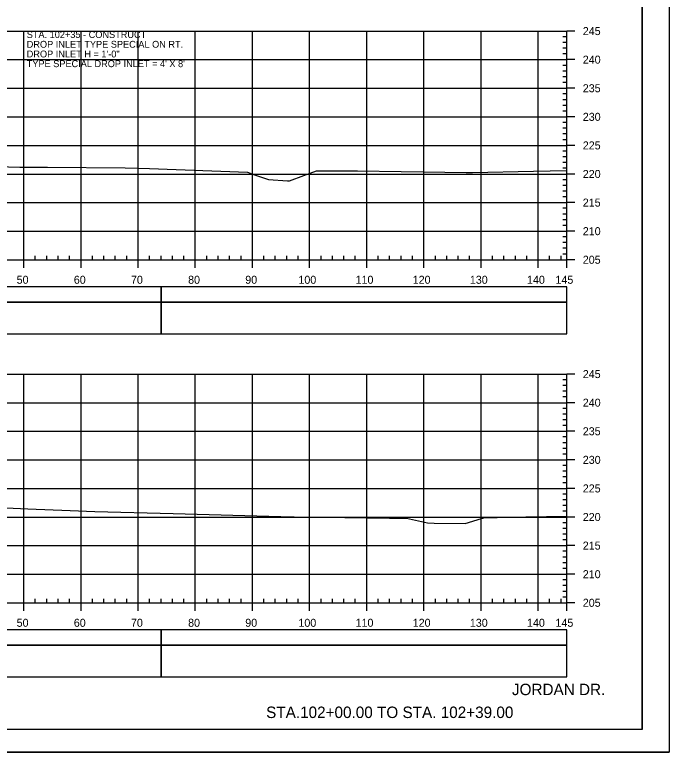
# Model space of a CAD drawing. Extents: x 1386544 to 1388153, y 379785 to 390999.
# Drawn here: x 1386933.6 to 1387048.2, y 380687.9 to 380816.9 of the extents above; entities that cross this region are included whole.
import ezdxf

# ---------------------------------------------------------------- set-up
doc = ezdxf.new("R2010")
doc.units = 0
for name, color, linetype in [('R_Axis', 7, 'Continuous'), ('R_Axis Annot', 7, 'Continuous'), ('R_Border', 7, 'Continuous'), ('R_Draft', 7, 'Continuous'), ('R_Exist Surface', 7, 'Continuous'), ('R_Grid', 7, 'Continuous'), ('R_No Plot', 7, 'Continuous'), ('R_Striping', 7, 'Continuous'), ('R_Water Annot', 7, 'Continuous')]:
    doc.layers.add(name, color=color, linetype=linetype)

msp = doc.modelspace()

# ---------------------------------------------------------------- linework, layer by layer
at = {"layer": 'R_Axis'}
for p, q in [((1387030.24, 380774.07), (1387030.24, 380814.07)), ((1387031.64, 380814.07), (1387030.24, 380814.07)), ((1387030.24, 380813.07), (1387029.54, 380813.07)), ((1387030.24, 380812.07), (1387029.54, 380812.07)), ((1387030.24, 380811.07), (1387029.54, 380811.07)), ((1387030.24, 380810.07), (1387029.54, 380810.07)), ((1387031.64, 380809.07), (1387030.24, 380809.07)), ((1387030.24, 380808.07), (1387029.54, 380808.07)), ((1387030.24, 380807.07), (1387029.54, 380807.07)), ((1387030.24, 380806.07), (1387029.54, 380806.07)), ((1387030.24, 380805.07), (1387029.54, 380805.07)), ((1387031.64, 380804.07), (1387030.24, 380804.07)), ((1387030.24, 380803.07), (1387029.54, 380803.07)), ((1387030.24, 380802.07), (1387029.54, 380802.07)), ((1387030.24, 380801.07), (1387029.54, 380801.07)), ((1387030.24, 380800.07), (1387029.54, 380800.07)), ((1387031.64, 380799.07), (1387030.24, 380799.07)), ((1387030.24, 380798.07), (1387029.54, 380798.07)), ((1387030.24, 380797.07), (1387029.54, 380797.07)), ((1387030.24, 380796.07), (1387029.54, 380796.07)), ((1387030.24, 380795.07), (1387029.54, 380795.07)), ((1387031.64, 380794.07), (1387030.24, 380794.07)), ((1387030.24, 380793.07), (1387029.54, 380793.07)), ((1387030.24, 380792.07), (1387029.54, 380792.07)), ((1387030.24, 380791.07), (1387029.54, 380791.07)), ((1387030.24, 380790.07), (1387029.54, 380790.07)), ((1387030.24, 380788.07), (1387029.54, 380788.07)), ((1387031.64, 380789.07), (1387030.24, 380789.07)), ((1387030.24, 380787.07), (1387029.54, 380787.07)), ((1387030.24, 380786.07), (1387029.54, 380786.07)), ((1387030.24, 380785.07), (1387029.54, 380785.07)), ((1387030.24, 380783.07), (1387029.54, 380783.07)), ((1387031.64, 380784.07), (1387030.24, 380784.07)), ((1387030.24, 380782.07), (1387029.54, 380782.07)), ((1387030.24, 380781.07), (1387029.54, 380781.07)), ((1387030.24, 380780.07), (1387029.54, 380780.07)), ((1387031.64, 380779.07), (1387030.24, 380779.07)), ((1387030.24, 380778.07), (1387029.54, 380778.07)), ((1387030.24, 380777.07), (1387029.54, 380777.07)), ((1387030.24, 380776.07), (1387029.54, 380776.07)), ((1386740.24, 380774.07), (1387030.24, 380774.07)), ((1386935.24, 380772.67), (1386935.24, 380774.07)), ((1386937.24, 380774.07), (1386937.24, 380774.77)), ((1386939.24, 380774.07), (1386939.24, 380774.77)), ((1386941.24, 380774.07), (1386941.24, 380774.77)), ((1386943.24, 380774.07), (1386943.24, 380774.77)), ((1386945.24, 380772.67), (1386945.24, 380774.07)), ((1386947.24, 380774.07), (1386947.24, 380774.77)), ((1386949.24, 380774.07), (1386949.24, 380774.77)), ((1386951.24, 380774.07), (1386951.24, 380774.77)), ((1386953.24, 380774.07), (1386953.24, 380774.77)), ((1386955.24, 380772.67), (1386955.24, 380774.07)), ((1386957.24, 380774.07), (1386957.24, 380774.77)), ((1386959.24, 380774.07), (1386959.24, 380774.77)), ((1386961.24, 380774.07), (1386961.24, 380774.77)), ((1386963.24, 380774.07), (1386963.24, 380774.77)), ((1386965.24, 380772.67), (1386965.24, 380774.07)), ((1386967.24, 380774.07), (1386967.24, 380774.77)), ((1386969.24, 380774.07), (1386969.24, 380774.77)), ((1386971.24, 380774.07), (1386971.24, 380774.77)), ((1386973.24, 380774.07), (1386973.24, 380774.77)), ((1386975.24, 380772.67), (1386975.24, 380774.07)), ((1386977.24, 380774.07), (1386977.24, 380774.77)), ((1386979.24, 380774.07), (1386979.24, 380774.77)), ((1386981.24, 380774.07), (1386981.24, 380774.77)), ((1386983.24, 380774.07), (1386983.24, 380774.77)), ((1386985.24, 380772.67), (1386985.24, 380774.07)), ((1386987.24, 380774.07), (1386987.24, 380774.77)), ((1386989.24, 380774.07), (1386989.24, 380774.77)), ((1386991.24, 380774.07), (1386991.24, 380774.77)), ((1386993.24, 380774.07), (1386993.24, 380774.77)), ((1386995.24, 380772.67), (1386995.24, 380774.07)), ((1386997.24, 380774.07), (1386997.24, 380774.77)), ((1386999.24, 380774.07), (1386999.24, 380774.77)), ((1387001.24, 380774.07), (1387001.24, 380774.77)), ((1387003.24, 380774.07), (1387003.24, 380774.77)), ((1387005.24, 380772.67), (1387005.24, 380774.07)), ((1387007.24, 380774.07), (1387007.24, 380774.77)), ((1387009.24, 380774.07), (1387009.24, 380774.77)), ((1387011.24, 380774.07), (1387011.24, 380774.77)), ((1387013.24, 380774.07), (1387013.24, 380774.77)), ((1387015.24, 380772.67), (1387015.24, 380774.07)), ((1387017.24, 380774.07), (1387017.24, 380774.77)), ((1387019.24, 380774.07), (1387019.24, 380774.77)), ((1387021.24, 380774.07), (1387021.24, 380774.77)), ((1387023.24, 380774.07), (1387023.24, 380774.77)), ((1387025.24, 380772.67), (1387025.24, 380774.07)), ((1387027.24, 380774.07), (1387027.24, 380774.77)), ((1387029.24, 380774.07), (1387029.24, 380774.77)), ((1387030.24, 380775.07), (1387029.54, 380775.07)), ((1387030.24, 380772.67), (1387030.24, 380774.07)), ((1387031.64, 380774.07), (1387030.24, 380774.07)), ((1387030.24, 380714.07), (1387030.24, 380754.07)), ((1387031.64, 380754.07), (1387030.24, 380754.07)), ((1387030.24, 380753.07), (1387029.54, 380753.07)), ((1387030.24, 380752.07), (1387029.54, 380752.07)), ((1387030.24, 380751.07), (1387029.54, 380751.07)), ((1387030.24, 380750.07), (1387029.54, 380750.07)), ((1387030.24, 380748.07), (1387029.54, 380748.07)), ((1387031.64, 380749.07), (1387030.24, 380749.07)), ((1387030.24, 380747.07), (1387029.54, 380747.07)), ((1387030.24, 380746.07), (1387029.54, 380746.07)), ((1387030.24, 380745.07), (1387029.54, 380745.07)), ((1387030.24, 380743.07), (1387029.54, 380743.07)), ((1387031.64, 380744.07), (1387030.24, 380744.07)), ((1387030.24, 380742.07), (1387029.54, 380742.07)), ((1387030.24, 380741.07), (1387029.54, 380741.07)), ((1387030.24, 380740.07), (1387029.54, 380740.07)), ((1387031.64, 380739.07), (1387030.24, 380739.07)), ((1387030.24, 380738.07), (1387029.54, 380738.07)), ((1387030.24, 380737.07), (1387029.54, 380737.07)), ((1387030.24, 380736.07), (1387029.54, 380736.07)), ((1387030.24, 380735.07), (1387029.54, 380735.07)), ((1387031.64, 380734.07), (1387030.24, 380734.07)), ((1387030.24, 380733.07), (1387029.54, 380733.07)), ((1387030.24, 380732.07), (1387029.54, 380732.07)), ((1387030.24, 380731.07), (1387029.54, 380731.07)), ((1387030.24, 380730.07), (1387029.54, 380730.07)), ((1387031.64, 380729.07), (1387030.24, 380729.07)), ((1387030.24, 380728.07), (1387029.54, 380728.07)), ((1387030.24, 380727.07), (1387029.54, 380727.07)), ((1387030.24, 380726.07), (1387029.54, 380726.07)), ((1387030.24, 380725.07), (1387029.54, 380725.07)), ((1387031.64, 380724.07), (1387030.24, 380724.07)), ((1387030.24, 380723.07), (1387029.54, 380723.07)), ((1387030.24, 380722.07), (1387029.54, 380722.07)), ((1387030.24, 380721.07), (1387029.54, 380721.07)), ((1387030.24, 380720.07), (1387029.54, 380720.07)), ((1387031.64, 380719.07), (1387030.24, 380719.07)), ((1387030.24, 380718.07), (1387029.54, 380718.07)), ((1387030.24, 380717.07), (1387029.54, 380717.07)), ((1387030.24, 380716.07), (1387029.54, 380716.07)), ((1386937.24, 380714.07), (1386937.24, 380714.77)), ((1386939.24, 380714.07), (1386939.24, 380714.77)), ((1386941.24, 380714.07), (1386941.24, 380714.77)), ((1386943.24, 380714.07), (1386943.24, 380714.77)), ((1386947.24, 380714.07), (1386947.24, 380714.77)), ((1386949.24, 380714.07), (1386949.24, 380714.77)), ((1386951.24, 380714.07), (1386951.24, 380714.77)), ((1386953.24, 380714.07), (1386953.24, 380714.77)), ((1386957.24, 380714.07), (1386957.24, 380714.77)), ((1386959.24, 380714.07), (1386959.24, 380714.77)), ((1386961.24, 380714.07), (1386961.24, 380714.77)), ((1386963.24, 380714.07), (1386963.24, 380714.77)), ((1386967.24, 380714.07), (1386967.24, 380714.77)), ((1386969.24, 380714.07), (1386969.24, 380714.77)), ((1386971.24, 380714.07), (1386971.24, 380714.77)), ((1386973.24, 380714.07), (1386973.24, 380714.77)), ((1386977.24, 380714.07), (1386977.24, 380714.77)), ((1386979.24, 380714.07), (1386979.24, 380714.77)), ((1386981.24, 380714.07), (1386981.24, 380714.77)), ((1386983.24, 380714.07), (1386983.24, 380714.77)), ((1386987.24, 380714.07), (1386987.24, 380714.77)), ((1386989.24, 380714.07), (1386989.24, 380714.77)), ((1386991.24, 380714.07), (1386991.24, 380714.77)), ((1386993.24, 380714.07), (1386993.24, 380714.77)), ((1386997.24, 380714.07), (1386997.24, 380714.77)), ((1386999.24, 380714.07), (1386999.24, 380714.77)), ((1387001.24, 380714.07), (1387001.24, 380714.77)), ((1387003.24, 380714.07), (1387003.24, 380714.77)), ((1387007.24, 380714.07), (1387007.24, 380714.77)), ((1387009.24, 380714.07), (1387009.24, 380714.77)), ((1387011.24, 380714.07), (1387011.24, 380714.77)), ((1387013.24, 380714.07), (1387013.24, 380714.77)), ((1387017.24, 380714.07), (1387017.24, 380714.77)), ((1387019.24, 380714.07), (1387019.24, 380714.77)), ((1387021.24, 380714.07), (1387021.24, 380714.77)), ((1387023.24, 380714.07), (1387023.24, 380714.77)), ((1387027.24, 380714.07), (1387027.24, 380714.77)), ((1387029.24, 380714.07), (1387029.24, 380714.77)), ((1387030.24, 380715.07), (1387029.54, 380715.07)), ((1386740.24, 380714.07), (1387030.24, 380714.07)), ((1386935.24, 380712.67), (1386935.24, 380714.07)), ((1386945.24, 380712.67), (1386945.24, 380714.07)), ((1386955.24, 380712.67), (1386955.24, 380714.07)), ((1386965.24, 380712.67), (1386965.24, 380714.07)), ((1386975.24, 380712.67), (1386975.24, 380714.07)), ((1386985.24, 380712.67), (1386985.24, 380714.07)), ((1386995.24, 380712.67), (1386995.24, 380714.07)), ((1387005.24, 380712.67), (1387005.24, 380714.07)), ((1387015.24, 380712.67), (1387015.24, 380714.07)), ((1387025.24, 380712.67), (1387025.24, 380714.07)), ((1387030.24, 380712.67), (1387030.24, 380714.07)), ((1387031.64, 380714.07), (1387030.24, 380714.07))]:
    msp.add_line(p, q, dxfattribs=at)
at = {"layer": 'R_Axis Annot'}
for points in [[(1386959.26, 380766.63), (1387030.24, 380766.63), (1387030.24, 380769.34), (1386959.26, 380769.34)], [(1386959.26, 380761.1), (1387030.24, 380761.1), (1387030.24, 380766.63), (1386959.26, 380766.63)], [(1386959.26, 380706.63), (1387030.24, 380706.63), (1387030.24, 380709.34), (1386959.26, 380709.34)], [(1386959.26, 380701.1), (1387030.24, 380701.1), (1387030.24, 380706.63), (1386959.26, 380706.63)]]:
    msp.add_lwpolyline(points, close=True, dxfattribs=at)
at = {"layer": 'R_Border'}
for q in [(1387043.42, 380897.37), (1386727.24, 380691.91)]:
    msp.add_line((1387043.42, 380691.91), q, dxfattribs=at)
at = {"layer": 'R_Exist Surface'}
for points in [[(1386924.43, 380790.54), (1386934.51, 380790.27), (1386936.18, 380790.27), (1386939.39, 380790.27), (1386952.98, 380790.12), (1386957.25, 380790.02), (1386974.37, 380789.39), (1386975.4, 380789), (1386978.02, 380788.09), (1386981.4, 380787.88), (1386981.75, 380787.87), (1386984.23, 380788.79), (1386986.46, 380789.62), (1386988.17, 380789.61), (1386993.6, 380789.61), (1387008.91, 380789.39), (1387012.66, 380789.35), (1387013.77, 380789.36), (1387024.43, 380789.57), (1387030.24, 380789.69)], [(1386926.87, 380730.93), (1386935.93, 380730.48), (1386943.35, 380730.2), (1386947.67, 380730.03), (1386961.38, 380729.66), (1386980.21, 380729.16), (1386982.56, 380729.11), (1386987.5, 380729.04), (1386999.24, 380728.89), (1387002.2, 380728.84), (1387004.28, 380728.41), (1387005.87, 380728.05), (1387007.04, 380728.02), (1387012.44, 380727.94), (1387015.34, 380728.81), (1387015.96, 380729.01), (1387018.03, 380729), (1387019.52, 380729.03), (1387030.24, 380729.23)]]:
    msp.add_lwpolyline(points, dxfattribs=at)
at = {"layer": 'R_Grid'}
for p, q in [((1386740.24, 380814.07), (1387030.24, 380814.07)), ((1386740.24, 380814.07), (1387030.24, 380814.07)), ((1386935.24, 380774.07), (1386935.24, 380814.07)), ((1386935.24, 380774.07), (1386935.24, 380814.07)), ((1386945.24, 380774.07), (1386945.24, 380814.07)), ((1386945.24, 380774.07), (1386945.24, 380814.07)), ((1386955.24, 380774.07), (1386955.24, 380814.07)), ((1386955.24, 380774.07), (1386955.24, 380814.07)), ((1386965.24, 380774.07), (1386965.24, 380814.07)), ((1386965.24, 380774.07), (1386965.24, 380814.07)), ((1386975.24, 380774.07), (1386975.24, 380814.07)), ((1386975.24, 380774.07), (1386975.24, 380814.07)), ((1386985.24, 380774.07), (1386985.24, 380814.07)), ((1386985.24, 380774.07), (1386985.24, 380814.07)), ((1386995.24, 380774.07), (1386995.24, 380814.07)), ((1386995.24, 380774.07), (1386995.24, 380814.07)), ((1387005.24, 380774.07), (1387005.24, 380814.07)), ((1387005.24, 380774.07), (1387005.24, 380814.07)), ((1387015.24, 380774.07), (1387015.24, 380814.07)), ((1387015.24, 380774.07), (1387015.24, 380814.07)), ((1387025.24, 380774.07), (1387025.24, 380814.07)), ((1387025.24, 380774.07), (1387025.24, 380814.07)), ((1387030.24, 380774.07), (1387030.24, 380814.07)), ((1387030.24, 380774.07), (1387030.24, 380814.07)), ((1386740.24, 380809.07), (1387030.24, 380809.07)), ((1386740.24, 380809.07), (1387030.24, 380809.07)), ((1386740.24, 380804.07), (1387030.24, 380804.07)), ((1386740.24, 380804.07), (1387030.24, 380804.07)), ((1386740.24, 380799.07), (1387030.24, 380799.07)), ((1386740.24, 380799.07), (1387030.24, 380799.07)), ((1386740.24, 380794.07), (1387030.24, 380794.07)), ((1386740.24, 380794.07), (1387030.24, 380794.07)), ((1386740.24, 380789.07), (1387030.24, 380789.07)), ((1386740.24, 380789.07), (1387030.24, 380789.07)), ((1386740.24, 380784.07), (1387030.24, 380784.07)), ((1386740.24, 380784.07), (1387030.24, 380784.07)), ((1386740.24, 380779.07), (1387030.24, 380779.07)), ((1386740.24, 380779.07), (1387030.24, 380779.07)), ((1386740.24, 380774.07), (1387030.24, 380774.07)), ((1386740.24, 380774.07), (1387030.24, 380774.07)), ((1386740.24, 380754.07), (1387030.24, 380754.07)), ((1386935.24, 380714.07), (1386935.24, 380754.07)), ((1386945.24, 380714.07), (1386945.24, 380754.07)), ((1386955.24, 380714.07), (1386955.24, 380754.07)), ((1386965.24, 380714.07), (1386965.24, 380754.07)), ((1386975.24, 380714.07), (1386975.24, 380754.07)), ((1386985.24, 380714.07), (1386985.24, 380754.07)), ((1386995.24, 380714.07), (1386995.24, 380754.07)), ((1387005.24, 380714.07), (1387005.24, 380754.07)), ((1387015.24, 380714.07), (1387015.24, 380754.07)), ((1387025.24, 380714.07), (1387025.24, 380754.07)), ((1387030.24, 380714.07), (1387030.24, 380754.07)), ((1386740.24, 380749.07), (1387030.24, 380749.07)), ((1386740.24, 380744.07), (1387030.24, 380744.07)), ((1386740.24, 380739.07), (1387030.24, 380739.07)), ((1386740.24, 380734.07), (1387030.24, 380734.07)), ((1386740.24, 380729.07), (1387030.24, 380729.07)), ((1386740.24, 380724.07), (1387030.24, 380724.07)), ((1386740.24, 380719.07), (1387030.24, 380719.07)), ((1386740.24, 380714.07), (1387030.24, 380714.07))]:
    msp.add_line(p, q, dxfattribs=at)
at = {"layer": 'R_No Plot'}
msp.add_line((1386714.84, 380687.93), (1387048.17, 380687.93), dxfattribs=at)
for points in [[(1386714.83, 380901.26), (1387048.17, 380901.26), (1387048.17, 380687.92), (1386714.83, 380687.92)], [(1386961.16, 380897.37), (1386980.78, 380897.37), (1386980.78, 380887.49), (1386996.89, 380887.49), (1387020.09, 380887.49), (1387020.09, 380863.15), (1387043.42, 380863.15), (1387043.42, 380691.91), (1386727.24, 380691.91), (1386727.24, 380897.37)]]:
    msp.add_lwpolyline(points, close=True, dxfattribs=at)
at = {"layer": 'R_Striping'}
for points in [[(1386927.92, 380766.63), (1386959.26, 380766.63), (1386959.26, 380769.34), (1386927.92, 380769.34)], [(1386927.92, 380761.11), (1386959.26, 380761.11), (1386959.26, 380766.63), (1386927.92, 380766.63)], [(1386927.92, 380706.63), (1386959.26, 380706.63), (1386959.26, 380709.34), (1386927.92, 380709.34)], [(1386927.92, 380701.11), (1386959.26, 380701.11), (1386959.26, 380706.63), (1386927.92, 380706.63)]]:
    msp.add_lwpolyline(points, close=True, dxfattribs=at)

# ---------------------------------------------------------------- texts
at = {"layer": 'R_Axis Annot'}
for s, p in [('245', (1387033.04, 380813.37)), ('240', (1387033.04, 380808.37)), ('235', (1387033.04, 380803.37)), ('230', (1387033.04, 380798.37)), ('225', (1387033.04, 380793.37)), ('220', (1387033.04, 380788.37)), ('215', (1387033.04, 380783.37)), ('210', (1387033.04, 380778.37)), ('205', (1387033.04, 380773.37)), ('50', (1386933.98, 380769.87)), ('60', (1386943.98, 380769.87)), ('70', (1386953.98, 380769.87)), ('80', (1386963.98, 380769.87)), ('90', (1386973.98, 380769.87)), ('100', (1386983.28, 380769.87)), ('110', (1386993.28, 380769.87)), ('120', (1387003.28, 380769.87)), ('130', (1387013.28, 380769.87)), ('140', (1387023.28, 380769.87)), ('145', (1387028.26, 380769.87)), ('245', (1387033.04, 380753.37)), ('240', (1387033.04, 380748.37)), ('235', (1387033.04, 380743.37)), ('230', (1387033.04, 380738.37)), ('225', (1387033.04, 380733.37)), ('220', (1387033.04, 380728.37)), ('215', (1387033.04, 380723.37)), ('210', (1387033.04, 380718.37)), ('205', (1387033.04, 380713.37)), ('50', (1386933.98, 380709.87)), ('60', (1386943.98, 380709.87)), ('70', (1386953.98, 380709.87)), ('80', (1386963.98, 380709.87)), ('90', (1386973.98, 380709.87)), ('100', (1386983.28, 380709.87)), ('110', (1386993.28, 380709.87)), ('120', (1387003.28, 380709.87)), ('130', (1387013.28, 380709.87)), ('140', (1387023.28, 380709.87)), ('145', (1387028.26, 380709.87))]:
    msp.add_text(s, height=1.4, dxfattribs=at).set_placement(p)
at = {"layer": 'R_Draft'}
for s, p in [('JORDAN DR.', (1387020.64, 380697.91)), ('STA.102+00.00 TO STA. 102+39.00', (1386977.63, 380693.91))]:
    msp.add_text(s, height=2, dxfattribs=at).set_placement(p)
at = {"layer": 'R_Water Annot'}
for s, p in [('STA. 102+35 - CONSTRUCT', (1386935.74, 380812.86)), ('DROP INLET TYPE SPECIAL ON RT.', (1386935.74, 380811.16)), ('DROP INLET H = 1\'-0"', (1386935.74, 380809.46)), ("TYPE SPECIAL DROP INLET = 4' X 8'", (1386935.74, 380807.76))]:
    msp.add_text(s, height=1.2, dxfattribs=at).set_placement(p)

doc.saveas('drawing.dxf')
